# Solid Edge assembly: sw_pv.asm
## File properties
Author: Sham
Template: Sync Iso Assembly.asm
Last saved by: TIET
Revision: 4
Application: Solid Edge
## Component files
base.par
Screw.par
moveable jaw.par
handle.par
handle screw.par
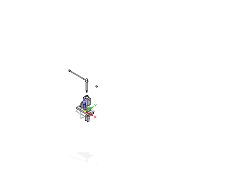
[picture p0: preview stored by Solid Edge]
